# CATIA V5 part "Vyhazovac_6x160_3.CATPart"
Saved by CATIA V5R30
Part number: Vyhazovac_6x160_3
Nomenclature: E1710/6x160
Description: MEUSBURGER
Property "Material": "1.221"
Publications: "__DrillHole", "Base"
Bounding box of the stored display mesh (mm): x -5.992 to 5.992, y -5.992 to 5.992, z 0 to 156.5
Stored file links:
  E:\Bakalarka\Model\Forma_v7\Vyhazovac_6x160_3.CATPart
  E:\dev\MoldDesign\intel_a\startup\components\MoldCatalog\Ejector\Meusburger\Ejector_E1710\TableE1710.txt
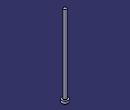
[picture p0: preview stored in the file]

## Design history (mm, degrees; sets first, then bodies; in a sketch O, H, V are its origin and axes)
Parameters
  Ref = "E1710/6x160" {design table}
  D1 = 6 mm {design table}
  D3 = 12 mm {design table}
  L = 160 mm {design table}
  L3 = 5 mm {design table}
  R = 0.5 mm {design table}
  k_d3 = 13 mm {design table}
  k_d1 = 6.2 mm {design table}
  k_F = 0.5 mm {design table}
  kl = 17 mm {design table}
  Mat = "1.221" {design table}
  HeatTreat = "ISO6751" {design table}
  Offset_Parting = 10 mm
  Anti_Rotation = "Normal"
  Anti_Rotation_D = 3.5 mm
  Anti_Rotation_D_Icut = 3.5 mm
  Add_Length_L = 1.8377 mm
  Add_Length_D3 = 0 mm
  SupplierRef = "Meusburger 2017"
  BmpRef = "F_MldEjectorD1"
  DrillHole_Length = 225 mm
  ValidationTest = false
  Anti_Rotation_D_min = 3.5 mm {= OffSet_D1 /2}
  Anti_Rotation_D_max = 5.925 mm {= D3/2-0.075mm}
  Anti_Rotation_D_ref = 3.5 mm {= Anti_Rotation_D}
  Anti_Rotation_D_Icut_ref = 3.5 mm {= Anti_Rotation_D_Icut}
  Anti_Rotation_Ref_Icut = 2.3246 mm
  Offset_L = 20 mm
  D = 6 mm {= D1}
  OffSet_D1 = 7 mm {= D1+2*R}
  OffSet_D3 = 13 mm {= D3+1mm}
  XG_Split = 100 mm
  YG_Split = -12 mm
  ZG_Split = -198 mm
  DirX_Split = 0 mm
  DirY_Split = 0 mm
  DirZ_Split = 1 mm
Set1 "BaseBody"
  Point1 "Base": (0, 0, 0)
  Plane1: type Offset, RefPlane xy-plane, Offset 225 {= DrillHole_Length}, reversed
  Sketch1 "Sketch.2" on xy-plane, origin (0, 0, 0), H (1, 0, 0), V (0, 1, 0)
    point P1 (-0.46, 1.1623)
    point P2 (0.46, 1.1623)
    construction line L1 (-0.46, 1.1623) -> (0.46, 1.1623)
    point P3 (0.46, -1.1623)
    line L2 (0.46, -1.1623) -> (0.46, 1.1623)
    point P4 (-0.46, -1.1623)
    construction line L3 (0.46, -1.1623) -> (-0.46, -1.1623)
    line L4 (-0.46, 1.1623) -> (-0.46, -1.1623)
    point P5 (-0.21, 1.1623)
    arc A1 centre (-0.21, 1.1623) radius 0.25 from (-0.21, 1.4123) to (-0.46, 1.1623) ccw
    point P7 (0.21, 1.1623)
    point P8 (0.21, 1.4123)
    arc A2 centre (0.21, 1.1623) radius 0.25 from (0.46, 1.1623) to (0.21, 1.4123) ccw
    line L5 (-0.21, 1.4123) -> (0.21, 1.4123)
    point P9 (-0.46, -1.1623)
    arc A3 centre (-0.21, -1.1623) radius 0.25 from (-0.46, -1.1623) to (-0.21, -1.4123) ccw
    point P11 (0.21, -1.4123)
    line L6 (-0.21, -1.4123) -> (0.21, -1.4123)
    point P12 (0.46, -1.1623)
    arc A4 centre (0.21, -1.1623) radius 0.25 from (0.21, -1.4123) to (0.46, -1.1623) ccw
    point P14 (-0.46, 1.1623)
    point P15 (-0.46, -1.1623)
    point P16 (0.46, 1.1623)
    point P17 (0.46, -1.1623)
    reference projected circle E1 centre (0, 0) radius 1.25 from edge [face of Shaft1 from Sketch2.L3 | face of Shaft1 from Sketch2.L4]
    reference projected circle E2 centre (0, 0) radius 1.25 from edge [face of Shaft1 from Sketch2.L3 | face of Shaft1 from Sketch2.L4]
    reference projected circle E3 centre (0, 0) radius 1.25 from edge [face of Shaft1 from Sketch2.L3 | face of Shaft1 from Sketch2.L4]
    reference projected circle E4 centre (0, 0) radius 1.25 from edge [face of Shaft1 from Sketch2.L3 | face of Shaft1 from Sketch2.L4]
    point P18 (-0.46, -1.1623)
    point P19 (-0.21, -1.4123)
    point P20 (0.21, -1.4123)
    point P21 (0.46, -1.1623)
    point P22 (-0.21, -1.4123)
    point P23 (0.21, -1.4123)
    distance P14 P15 = 2.3246 (reference)
    distance P16 P17 = 2.3246 (reference)
    distance L1 P14 = 0 (reference)
    radius A1 = 3
    distance L4 V = 3.51
    distance L2 V = 5.935
    distance L5 L6 = 12
    horizontal: L1 H, L3 H, L5 H
    vertical: L2 V, L4 V
    coincidence: P5 L1, P7 L1, P3 P12, P14 L4, P15 L4, P16 L2, P17 L2, P14 E1, P15 E2, P16 E3, P17 E4, P3 P21, P4 P18, P20 P23, P19 P22
    tangency: A1 L4, A2 L2, A2 L5, A1 L5
    symmetry: P1 P9 H, A1 A3 H, P8 P11 H, L5 L6 H, P2 P12 H, A2 A4 H
  DatumSurface1
Body1 "PartBody" (main body)
  Sketch2 "Sketch.1" on zx-plane, origin (0, 0, 0), H (-1, 0, 0), V (0, 0, 1)
    point P1 (0, 160)
    line L1 (3, 160) -> (0, 160)
    line L2 (3, 5) -> (3, 160)
    line L3 (6, 5) -> (3, 5)
    line L4 (6, 0) -> (6, 5)
    point P5 (0, 0)
    line L5 (0, 0) -> (6, 0)
    point P6 (0, 160)
    axis line L6 (0, 160) -> (0, 0)
    point P7 (0, 0)
    point P8 (3, 5)
    point P9 (3, 5)
    line L7 (0, 160) -> (0, 0)
    distance L5 L3 = 5 {= L3}
    distance L5 L1 = 160 {= L}
    distance L2 L6 = 3 {= D1 /2}
    distance L4 L6 = 6 {= D3 /2}
    coincidence: L6 P5, P1 L6, L5 H, L6 V, P7 O, P6 P1, P8 P9
    vertical: L2 V, L7 V
    horizontal: L1 H
  Shaft1 "Shaft.1": profile Sketch2, axis Sketch2.L6, angle 360
  Pocket1 "Pocket.1": profile Sketch1, direction (0, 0, 1), length 6, outer side, deactivated
  Pocket2 "Pocket.2": profile Sketch1, direction (0, 0, 1), length 6, outer side, deactivated
  Fillet1: radius 0.5 {= R}, on edge [face of Shaft1 from Sketch2.L2 | face of Shaft1 from Sketch2.L3]
  Pocket3: profile face of Shaft1 from Sketch2.L1, direction along face of Shaft1 from Sketch2.L1 reversed, up to face of DatumSurface1
Body2 "__DrillHole"
  Sketch3 "Sketch.3" on face of Shaft1, origin (0, 0, 0), H (1, 0, 0), V (0, -1, 0)
    point P1 (0, 0)
    reference projected point E1 (0, 0) from Point1
    coincidence: E1 P1
  Hole1 "Hole.1": placed by Sketch3, at (0, 0, 0) direction (0, 0, 1), diameter 7 {= OffSet_D1}, depth 140 {= L-Offset_L}
  Sketch4 "Sketch.4" on face of Shaft1, origin (0, 0, 0), H (1, 0, 0), V (0, -1, 0)
    point P1 (0, 0)
    reference projected point E1 (0, 0) from Point1
    coincidence: E1 P1
  Hole2 "Hole.2": placed by Sketch4, at (0, 0, 0) direction (0, 0, 1), diameter 6 {= D1}, depth 160 {= L}
  Sketch5 "Sketch.5" on face of Shaft1 from Sketch2.L3, origin (0, 0, 5), H (1, 0, 0), V (0, 1, 0)
    point P1 (0, 0)
    reference projected point E1 (0, 0) from Point1
    coincidence: E1 P1
  Hole3 "Hole.3": placed by Sketch5, at (0, 0, 5) direction (0, 0, -1), diameter 13 {= OffSet_D3}, depth 230 {= L3 +DrillHole_Length}
  Chamfer1: length 0.5 {= k_F}, angle 45, on edge [face of Hole1 | face of Hole3]
  Body3 "__Body.1"
    Pocket4 "Pocket.3": profile Sketch1, direction (0, 0, -1), length 225, opposite side length 5, deactivated
  Assemble1: tool Body3
  Chamfer2: length 0.5 {= k_F}, angle 45, on edge [start face of Pocket4 | face of Hole1], deactivated
  Body4 "__Body.2"
    Pocket5 "Pocket.4": profile Sketch1, direction (0, 0, -1), length 225, opposite side length 5, deactivated
  Assemble2: tool Body4
  Chamfer3: length 0.5 {= k_F}, angle 45, on edge [start face of Pocket5 | face of Hole1], deactivated
Relations
  design table "TableE1710", configuration 254, drives Ref, D1, D3, L, L3, R, k_d3, k_d1, k_F, kl, Mat, HeatTreat
  Offset_L = 20mm (deactivated)
  rule "Cut_Head_rule":
    let sketch_cut (length)
    let PartBody_Pocket_Sketch (Boolean)
    let I_PartBody_Pocket (Boolean)
    let D_PartBody_Pocket (Boolean)
    let N_DrillHole_Hole (Boolean)
    let N_DrillHole_Hole_Sketch (Boolean)
    let I_DrillHole_Pocket (Boolean)
    let D_DrillHole_Pocket (Boolean)
    /* --------------------------------------------------------------------------------------*/
    if Anti_Rotation =="Normal"
    {
    	sketch_cut=Anti_Rotation_D_max
    	PartBody_Pocket_Sketch = false
    	I_PartBody_Pocket = false
    	D_PartBody_Pocket = false
    	N_DrillHole_Hole = true
    	N_DrillHole_Hole_Sketch = true
    	I_DrillHole_Pocket = false
    	D_DrillHole_Pocket = false
    	Chamfer1.Activity= true
    	Chamfer2.Activity= false
    	Chamfer3.Activity= false
    }
    if Anti_Rotation == "I_Cut"
    {
    	sketch_cut=Anti_Rotation_D_Icut_ref
    	PartBody_Pocket_Sketch = true
    	I_PartBody_Pocket = true
    	D_PartBody_Pocket = false
    	N_DrillHole_Hole = false
    	N_DrillHole_Hole_Sketch = false
    	I_DrillHole_Pocket = true
    	D_DrillHole_Pocket = false
    	Chamfer1.Activity= false
    	Chamfer2.Activity= true
    	Chamfer3.Activity= false
    }
    if Anti_Rotation =="D_Cut"
    {
    	sketch_cut=Anti_Rotation_D_max
    	PartBody_Pocket_Sketch = true
    	I_PartBody_Pocket = false
    	D_PartBody_Pocket = true
    	N_DrillHole_Hole = false
    	N_DrillHole_Hole_Sketch = false
    	I_DrillHole_Pocket = false
    	D_DrillHole_Pocket = true
    	Chamfer1.Activity= false
    	Chamfer2.Activity= false
    	Chamfer3.Activity= true
    }
    /* --------------------------------------------------------------------------------------*/
    Sketch1.distance(L2 V) = sketch_cut+0.01mm
    Sketch1.distance(L4 V) =Anti_Rotation_D_ref+0.01mm
    Sketch1.radius(A1) =D/2
    Pocket4.FirstLimit.Depth = DrillHole_Length
    Pocket5.FirstLimit.Depth = DrillHole_Length
    Pocket1.FirstLimit.Depth = L3+1mm
    Pocket2.FirstLimit.Depth = L3+1mm
    Pocket4.SecondLimit.Depth = L3
    Pocket5.SecondLimit.Depth =L3
    Pocket1.Activity = I_PartBody_Pocket
    Pocket2.Activity = D_PartBody_Pocket
    Sketch1.Activity =PartBody_Pocket_Sketch
    Hole3.Activity= N_DrillHole_Hole
    Sketch5.Activity = N_DrillHole_Hole_Sketch
    Pocket4.Activity = I_DrillHole_Pocket
    Pocket5.Activity  = D_DrillHole_Pocket
  rule "Anti_Rotation_Icut_constrain":
    let Ref1(length)
    let Ref2(length)
    let Ref3(length)
    let Diam1(length)
    let Diam2(length)
    let Add_Length_Lmin (length)
    Ref1=Sketch1.distance(P14 P15)
    Ref2=Sketch1.distance(P16 P17)
    Diam1=D
    Diam2=D3
    /* --------------------------------------------------------------------*/
    if Ref1 >Ref2
    	Anti_Rotation_Ref_Icut = Ref1
    else
    	Anti_Rotation_Ref_Icut  =Ref2
    Add_Length_D3 .InferiorRange=Anti_Rotation_Ref_Icut /2+Diam1/2 -Diam2/2
    if Add_Length_D3 .InferiorRange<0mm
    	Add_Length_D3 .InferiorRange=0mm
    if ValidationTest == "true"
    	Ref3   = 2*Add_Length_L +Anti_Rotation_Ref_Icut  +2*Diam1/2
    else
    	Ref3  =Diam2+2*Add_Length_D3
    if Ref3 <Diam2
    {
    	Ref3 =Diam2
    }
    /* --------------------------------------------------------------------*/
    Sketch1.distance(L5 L6) = Ref3
    Add_Length_L .InferiorRange=Diam2/2-Anti_Rotation_Ref_Icut/2-Diam1/2
    Add_Length_Lmin=Diam2/2-Anti_Rotation_Ref_Icut/2-Diam1/2
    if Add_Length_Lmin<0mm
    	Add_Length_L .InferiorRange=0mm
    else
    	Add_Length_L .InferiorRange=Add_Length_Lmin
